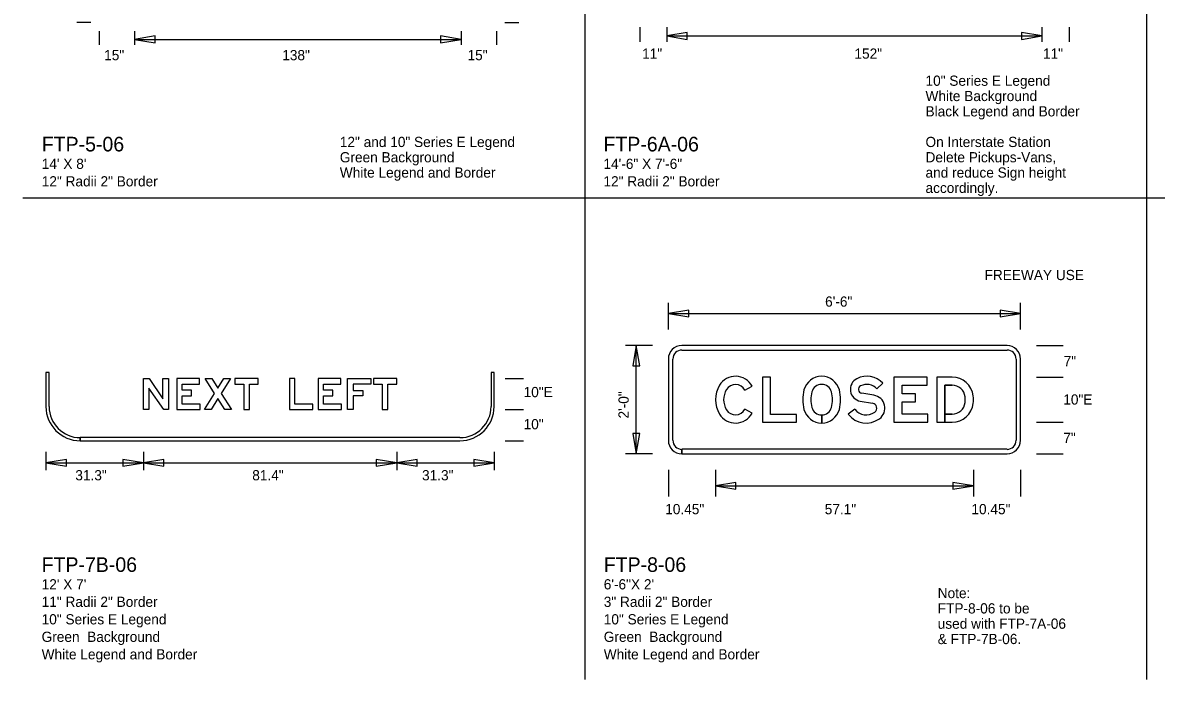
# Model space of a CAD drawing. Extents: x 0 to 770, y 0 to 495.
# Drawn here: x 0 to 388.5, y 0 to 225.2 of the extents above; entities that cross this region are included whole.
import ezdxf

# ---------------------------------------------------------------- set-up
doc = ezdxf.new("R2010")
doc.units = 0
for name, color, linetype in [('Dimension', 7, 'Continuous'), ('GSBWFill', 7, 'Continuous'), ('GSColorFill', 7, 'Continuous'), ('GSDims', 7, 'Continuous'), ('GSOutline', 7, 'Continuous'), ('SheetLines_dp', 7, 'Continuous'), ('TextStructures', 7, 'Continuous')]:
    doc.layers.add(name, color=color, linetype=linetype)

msp = doc.modelspace()

# ---------------------------------------------------------------- linework, layer by layer
at = {"layer": 'Dimension'}
for points in [[(220.78, 220.64), (227.79, 219.46), (227.79, 221.83)], [(349.34, 220.64), (342.33, 221.83), (342.33, 219.46)], [(38.38, 219.43), (45.4, 218.25), (45.4, 220.62)], [(150.27, 219.43), (143.25, 220.62), (143.25, 218.25)], [(221.28, 125.44), (228.3, 124.25), (228.3, 126.63)], [(342, 125.44), (334.99, 126.63), (334.99, 124.25)], [(210.31, 114.47), (209.12, 107.46), (211.5, 107.46)], [(210.31, 77.33), (211.5, 84.34), (209.12, 84.34)], [(7.98, 74.26), (14.99, 73.07), (14.99, 75.44)], [(41.37, 74.26), (34.35, 75.44), (34.35, 73.07)], [(41.37, 74.26), (48.39, 73.07), (48.39, 75.44)], [(128.21, 74.26), (121.19, 75.44), (121.19, 73.07)], [(128.21, 74.26), (135.22, 73.07), (135.22, 75.44)], [(161.6, 74.26), (154.58, 75.44), (154.58, 73.07)], [(237.45, 66.36), (244.47, 65.17), (244.47, 67.55)], [(325.83, 66.36), (318.81, 67.55), (318.81, 65.17)]]:
    msp.add_lwpolyline(points, close=True, dxfattribs=at)
at = {"layer": 'GSBWFill'}
for p, q in [((337.36, 114.47), (225.92, 114.47)), ((337.36, 114.47), (225.92, 114.47)), ((225.92, 112.93), (337.36, 112.93)), ((221.28, 109.83), (221.28, 81.97)), ((221.28, 109.83), (221.28, 81.97)), ((222.83, 81.97), (222.83, 109.83)), ((340.46, 109.83), (340.46, 81.97)), ((342, 81.97), (342, 109.83)), ((342, 81.97), (342, 109.83)), ((7.98, 105.19), (7.98, 93.55)), ((7.98, 105.19), (7.98, 93.55)), ((9.04, 93.55), (9.04, 105.19)), ((160.53, 105.19), (160.53, 93.55)), ((161.6, 93.55), (161.6, 105.19)), ((161.6, 93.55), (161.6, 105.19)), ((292.76, 99.62), (294.8, 101.51)), ((247.53, 99.2), (249.99, 100.51)), ((291.75, 97.43), (287.54, 98.14)), ((287.07, 95.4), (291.29, 94.68)), ((249.99, 91.3), (247.53, 92.61)), ((247.53, 92.61), (247.53, 92.61)), ((273.83, 87.89), (273.83, 90.68)), ((273.83, 90.68), (273.83, 87.89)), ((285.17, 92.61), (282.96, 90.91)), ((316.08, 88.16), (318.53, 88.16)), ((19.71, 81.82), (19.71, 82.88)), ((19.71, 81.82), (149.86, 81.82)), ((149.86, 82.88), (19.72, 82.88)), ((19.72, 82.88), (19.72, 81.82)), ((19.72, 81.82), (149.86, 81.82)), ((225.92, 77.33), (225.92, 78.88)), ((337.36, 78.88), (225.94, 78.88)), ((225.94, 78.88), (225.94, 77.33)), ((225.92, 77.33), (337.36, 77.33)), ((225.94, 77.33), (337.36, 77.33))]:
    msp.add_line(p, q, dxfattribs=at)
for points in [[(9.04, 105.19), (7.98, 105.19)], [(161.6, 105.19), (160.53, 105.19)], [(318.53, 103.64), (313.29, 103.64), (313.29, 88.16), (316.08, 88.16), (316.08, 100.85), (318.53, 100.85)], [(318.53, 90.95), (316.08, 90.95), (316.08, 88.16)]]:
    msp.add_lwpolyline(points, dxfattribs=at)
for points in [[(50.01, 103.15), (50.01, 92.48), (48.36, 92.48), (43.29, 99.79), (43.29, 92.48), (41.37, 92.48), (41.37, 103.15), (43.3, 103.15), (48.09, 96.24), (48.09, 103.15)], [(60.78, 94.41), (54.7, 94.41), (54.7, 97.27), (57.85, 97.27), (57.85, 99.19), (54.7, 99.19), (54.7, 101.23), (60.62, 101.23), (60.62, 103.15), (52.78, 103.15), (52.78, 92.48), (60.78, 92.48)], [(69.29, 92.48), (66.92, 96.27), (64.55, 92.48), (62.28, 92.48), (65.79, 98.07), (62.6, 103.15), (64.87, 103.15), (66.92, 99.88), (68.97, 103.15), (71.24, 103.15), (68.05, 98.07), (71.56, 92.48)], [(72.73, 101.23), (75.77, 101.23), (75.77, 92.48), (77.69, 92.48), (77.69, 101.23), (80.73, 101.23), (80.73, 103.15), (72.73, 103.15)], [(99.4, 92.48), (99.4, 94.35), (93.32, 94.35), (93.32, 103.15), (91.4, 103.15), (91.4, 92.48)], [(109.22, 94.41), (103.14, 94.41), (103.14, 97.27), (106.28, 97.27), (106.28, 99.19), (103.14, 99.19), (103.14, 101.23), (109.06, 101.23), (109.06, 103.15), (101.22, 103.15), (101.22, 92.48), (109.22, 92.48)], [(113.27, 97.18), (113.27, 92.48), (111.35, 92.48), (111.35, 103.15), (119.35, 103.15), (119.35, 101.23), (113.27, 101.23), (113.27, 99.1), (116.63, 99.1), (116.63, 97.18)], [(120.21, 101.23), (123.25, 101.23), (123.25, 92.48), (125.17, 92.48), (125.17, 101.23), (128.21, 101.23), (128.21, 103.15), (120.21, 103.15)], [(265.16, 88.16), (265.16, 90.87), (256.34, 90.87), (256.34, 103.64), (253.55, 103.64), (253.55, 88.16)], [(310.2, 90.95), (301.38, 90.95), (301.38, 95.11), (305.94, 95.11), (305.94, 97.9), (301.38, 97.9), (301.38, 100.85), (309.97, 100.85), (309.97, 103.64), (298.59, 103.64), (298.59, 88.16), (310.2, 88.16)]]:
    msp.add_lwpolyline(points, close=True, dxfattribs=at)
for centre, radius, start, end in [((225.92, 109.83), 4.64, 90, 180), ((225.92, 109.83), 4.64, 90, 180), ((225.92, 109.83), 3.1, 90, 180), ((337.36, 109.83), 4.64, 0, 90), ((337.36, 109.83), 4.64, 0, 90), ((337.36, 109.83), 3.1, 0, 90), ((244.32, 97.49), 6.42, 28.0265, 148.7499), ((244.32, 97.49), 3.64, 28.0265, 148.7499), ((273.83, 97.64), 6.27, 14.9618, 165.0382), ((273.83, 97.64), 3.49, 14.9618, 165.0382), ((287.76, 99.44), 4.1, 116.9123, 260.4087), ((289.3, 96.4), 7.51, 42.8759, 116.9123), ((289.3, 96.4), 4.72, 42.8759, 116.9123), ((318.53, 96.36), 7.27, 6.5003, 90), ((246.94, 95.9), 9.48, 148.7499, 211.2501), ((246.94, 95.9), 6.7, 148.7499, 211.2501), ((280.33, 95.9), 13, 165.0382, 194.9618), ((280.33, 95.9), 10.22, 165.0382, 194.9618), ((267.33, 95.9), 10.22, 345.0382, 14.9618), ((267.33, 95.9), 13, 345.0382, 14.9618), ((287.76, 99.44), 1.32, 116.9123, 260.4087), ((291.01, 93), 4.49, 306.123, 80.4087), ((318.53, 96.36), 4.49, 6.5002, 90), ((314.45, 95.9), 11.38, 353.4998, 6.5002), ((19.71, 93.55), 11.73, 180, 270), ((19.71, 93.55), 11.73, 180, 270), ((19.71, 93.55), 10.67, 180, 270), ((149.86, 93.55), 10.67, 270, 0), ((149.86, 93.55), 11.73, 270, 0), ((149.86, 93.55), 11.73, 270, 0), ((273.83, 94.16), 3.49, 194.9618, 270), ((273.83, 94.16), 3.49, 270.0127, 345.0382), ((291.01, 93), 1.7, 306.123, 80.4087), ((318.53, 95.44), 4.49, 270, 353.4998), ((318.53, 95.44), 7.27, 270, 353.4998), ((314.45, 95.9), 8.59, 353.4998, 6.5003), ((244.32, 94.31), 6.42, 211.2501, 331.9735), ((244.32, 94.31), 3.64, 211.2501, 331.9735), ((273.83, 94.16), 6.27, 194.9618, 270), ((273.83, 94.16), 6.27, 270.0071, 345.0382), ((289.09, 95.63), 7.74, 217.5895, 306.123), ((289.09, 95.63), 4.95, 217.5895, 306.123), ((225.92, 81.97), 4.64, 180, 270), ((225.92, 81.97), 4.64, 180, 270), ((225.92, 81.97), 3.1, 180, 270), ((337.36, 81.97), 4.64, 270, 0), ((337.36, 81.97), 3.1, 270, 0), ((337.36, 81.97), 4.64, 270, 0)]:
    msp.add_arc(centre, radius, start, end, dxfattribs=at)
at = {"layer": 'GSColorFill'}
for p, q in [((292.76, 99.62), (294.8, 101.51)), ((247.53, 99.2), (249.99, 100.51)), ((291.75, 97.43), (287.54, 98.14)), ((287.07, 95.4), (291.29, 94.68)), ((249.99, 91.3), (247.53, 92.61)), ((247.53, 92.61), (247.53, 92.61)), ((273.83, 87.89), (273.83, 90.68)), ((273.83, 90.68), (273.83, 87.89)), ((285.17, 92.61), (282.96, 90.91)), ((316.08, 88.16), (318.53, 88.16))]:
    msp.add_line(p, q, dxfattribs=at)
for points in [[(50.01, 103.15), (50.01, 92.48), (48.36, 92.48), (43.29, 99.79), (43.29, 92.48), (41.37, 92.48), (41.37, 103.15), (43.3, 103.15), (48.09, 96.24), (48.09, 103.15)], [(60.78, 94.41), (54.7, 94.41), (54.7, 97.27), (57.85, 97.27), (57.85, 99.19), (54.7, 99.19), (54.7, 101.23), (60.62, 101.23), (60.62, 103.15), (52.78, 103.15), (52.78, 92.48), (60.78, 92.48)], [(69.29, 92.48), (66.92, 96.27), (64.55, 92.48), (62.28, 92.48), (65.79, 98.07), (62.6, 103.15), (64.87, 103.15), (66.92, 99.88), (68.97, 103.15), (71.24, 103.15), (68.05, 98.07), (71.56, 92.48)], [(72.73, 101.23), (75.77, 101.23), (75.77, 92.48), (77.69, 92.48), (77.69, 101.23), (80.73, 101.23), (80.73, 103.15), (72.73, 103.15)], [(99.4, 92.48), (99.4, 94.35), (93.32, 94.35), (93.32, 103.15), (91.4, 103.15), (91.4, 92.48)], [(109.22, 94.41), (103.14, 94.41), (103.14, 97.27), (106.28, 97.27), (106.28, 99.19), (103.14, 99.19), (103.14, 101.23), (109.06, 101.23), (109.06, 103.15), (101.22, 103.15), (101.22, 92.48), (109.22, 92.48)], [(113.27, 97.18), (113.27, 92.48), (111.35, 92.48), (111.35, 103.15), (119.35, 103.15), (119.35, 101.23), (113.27, 101.23), (113.27, 99.1), (116.63, 99.1), (116.63, 97.18)], [(120.21, 101.23), (123.25, 101.23), (123.25, 92.48), (125.17, 92.48), (125.17, 101.23), (128.21, 101.23), (128.21, 103.15), (120.21, 103.15)], [(265.16, 88.16), (265.16, 90.87), (256.34, 90.87), (256.34, 103.64), (253.55, 103.64), (253.55, 88.16)], [(310.2, 90.95), (301.38, 90.95), (301.38, 95.11), (305.94, 95.11), (305.94, 97.9), (301.38, 97.9), (301.38, 100.85), (309.97, 100.85), (309.97, 103.64), (298.59, 103.64), (298.59, 88.16), (310.2, 88.16)]]:
    msp.add_lwpolyline(points, close=True, dxfattribs=at)
for points in [[(318.53, 103.64), (313.29, 103.64), (313.29, 88.16), (316.08, 88.16), (316.08, 100.85), (318.53, 100.85)], [(318.53, 90.95), (316.08, 90.95), (316.08, 88.16)]]:
    msp.add_lwpolyline(points, dxfattribs=at)
for centre, radius, start, end in [((244.32, 97.49), 6.42, 28.0265, 148.7499), ((244.32, 97.49), 3.64, 28.0265, 148.7499), ((273.83, 97.64), 6.27, 14.9618, 165.0382), ((273.83, 97.64), 3.49, 14.9618, 165.0382), ((287.76, 99.44), 4.1, 116.9123, 260.4087), ((289.3, 96.4), 7.51, 42.8759, 116.9123), ((289.3, 96.4), 4.72, 42.8759, 116.9123), ((318.53, 96.36), 7.27, 6.5003, 90), ((246.94, 95.9), 9.48, 148.7499, 211.2501), ((246.94, 95.9), 6.7, 148.7499, 211.2501), ((280.33, 95.9), 13, 165.0382, 194.9618), ((280.33, 95.9), 10.22, 165.0382, 194.9618), ((267.33, 95.9), 10.22, 345.0382, 14.9618), ((267.33, 95.9), 13, 345.0382, 14.9618), ((287.76, 99.44), 1.32, 116.9123, 260.4087), ((291.01, 93), 4.49, 306.123, 80.4087), ((318.53, 96.36), 4.49, 6.5002, 90), ((314.45, 95.9), 11.38, 353.4998, 6.5002), ((273.83, 94.16), 3.49, 194.9618, 270), ((273.83, 94.16), 3.49, 270.0127, 345.0382), ((291.01, 93), 1.7, 306.123, 80.4087), ((318.53, 95.44), 4.49, 270, 353.4998), ((318.53, 95.44), 7.27, 270, 353.4998), ((314.45, 95.9), 8.59, 353.4998, 6.5003), ((244.32, 94.31), 6.42, 211.2501, 331.9735), ((244.32, 94.31), 3.64, 211.2501, 331.9735), ((273.83, 94.16), 6.27, 194.9618, 270), ((273.83, 94.16), 6.27, 270.0071, 345.0382), ((289.09, 95.63), 7.74, 217.5895, 306.123), ((289.09, 95.63), 4.95, 217.5895, 306.123)]:
    msp.add_arc(centre, radius, start, end, dxfattribs=at)
at = {"layer": 'GSDims'}
for p, q in [((23.35, 225.18), (18.56, 225.18)), ((26.22, 222.31), (26.22, 217.52)), ((38.38, 222.31), (38.38, 217.52)), ((38.38, 222.31), (38.38, 217.52)), ((150.27, 222.31), (150.27, 217.52)), ((150.27, 222.31), (150.27, 217.52)), ((162.43, 222.31), (162.43, 217.52)), ((165.3, 225.18), (170.09, 225.18)), ((211.47, 223.64), (211.47, 218.65)), ((220.78, 223.64), (220.78, 218.65)), ((220.78, 223.64), (220.78, 218.65)), ((349.34, 223.64), (349.34, 218.65)), ((349.34, 223.64), (349.34, 218.65)), ((358.65, 223.64), (358.65, 218.65)), ((38.38, 219.43), (150.27, 219.43)), ((220.78, 220.64), (349.34, 220.64)), ((221.28, 119.96), (221.28, 129.1)), ((342, 119.96), (342, 129.1)), ((221.28, 125.44), (342, 125.44)), ((215.8, 114.47), (206.65, 114.47)), ((210.31, 77.33), (210.31, 114.47)), ((347.49, 114.47), (356.63, 114.47)), ((165.38, 103.15), (171.68, 103.15)), ((165.38, 103.15), (171.68, 103.15)), ((347.49, 103.64), (356.63, 103.64)), ((347.49, 103.64), (356.63, 103.64)), ((165.38, 92.48), (171.68, 92.48)), ((165.38, 92.48), (171.68, 92.48)), ((347.49, 88.16), (356.63, 88.16)), ((347.49, 88.16), (356.63, 88.16)), ((165.38, 81.82), (171.68, 81.82)), ((7.98, 78.04), (7.98, 71.74)), ((41.37, 78.04), (41.37, 71.74)), ((41.37, 78.04), (41.37, 71.74)), ((128.21, 78.04), (128.21, 71.74)), ((128.21, 78.04), (128.21, 71.74)), ((161.6, 78.04), (161.6, 71.74)), ((7.98, 74.26), (41.37, 74.26)), ((41.37, 74.26), (128.21, 74.26)), ((128.21, 74.26), (161.6, 74.26)), ((215.8, 77.33), (206.65, 77.33)), ((347.49, 77.33), (356.63, 77.33)), ((221.28, 71.84), (221.28, 62.7)), ((237.45, 71.84), (237.45, 62.7)), ((237.45, 71.84), (237.45, 62.7)), ((325.83, 71.84), (325.83, 62.7)), ((325.83, 71.84), (325.83, 62.7)), ((342, 71.84), (342, 62.7)), ((237.45, 66.36), (325.83, 66.36))]:
    msp.add_line(p, q, dxfattribs=at)
at = {"layer": 'GSOutline'}
for p, q in [((292.76, 99.62), (294.8, 101.51)), ((247.53, 99.2), (249.99, 100.51)), ((291.75, 97.43), (287.54, 98.14)), ((287.07, 95.4), (291.29, 94.68)), ((249.99, 91.3), (247.53, 92.61)), ((247.53, 92.61), (247.53, 92.61)), ((285.17, 92.61), (282.96, 90.91)), ((316.08, 90.95), (318.53, 90.95))]:
    msp.add_line(p, q, dxfattribs=at)
for points in [[(50.01, 103.15), (50.01, 92.48), (48.36, 92.48), (43.29, 99.79), (43.29, 92.48), (41.37, 92.48), (41.37, 103.15), (43.3, 103.15), (48.09, 96.24), (48.09, 103.15)], [(60.78, 94.41), (54.7, 94.41), (54.7, 97.27), (57.85, 97.27), (57.85, 99.19), (54.7, 99.19), (54.7, 101.23), (60.62, 101.23), (60.62, 103.15), (52.78, 103.15), (52.78, 92.48), (60.78, 92.48)], [(69.29, 92.48), (66.92, 96.27), (64.55, 92.48), (62.28, 92.48), (65.79, 98.07), (62.6, 103.15), (64.87, 103.15), (66.92, 99.88), (68.97, 103.15), (71.24, 103.15), (68.05, 98.07), (71.56, 92.48)], [(72.73, 101.23), (75.77, 101.23), (75.77, 92.48), (77.69, 92.48), (77.69, 101.23), (80.73, 101.23), (80.73, 103.15), (72.73, 103.15)], [(99.4, 92.48), (99.4, 94.35), (93.32, 94.35), (93.32, 103.15), (91.4, 103.15), (91.4, 92.48)], [(109.22, 94.41), (103.14, 94.41), (103.14, 97.27), (106.28, 97.27), (106.28, 99.19), (103.14, 99.19), (103.14, 101.23), (109.06, 101.23), (109.06, 103.15), (101.22, 103.15), (101.22, 92.48), (109.22, 92.48)], [(113.27, 97.18), (113.27, 92.48), (111.35, 92.48), (111.35, 103.15), (119.35, 103.15), (119.35, 101.23), (113.27, 101.23), (113.27, 99.1), (116.63, 99.1), (116.63, 97.18)], [(120.21, 101.23), (123.25, 101.23), (123.25, 92.48), (125.17, 92.48), (125.17, 101.23), (128.21, 101.23), (128.21, 103.15), (120.21, 103.15)], [(265.16, 88.16), (265.16, 90.87), (256.34, 90.87), (256.34, 103.64), (253.55, 103.64), (253.55, 88.16)], [(310.2, 90.95), (301.38, 90.95), (301.38, 95.11), (305.94, 95.11), (305.94, 97.9), (301.38, 97.9), (301.38, 100.85), (309.97, 100.85), (309.97, 103.64), (298.59, 103.64), (298.59, 88.16), (310.2, 88.16)]]:
    msp.add_lwpolyline(points, close=True, dxfattribs=at)
for points in [[(318.53, 103.64), (313.29, 103.64), (313.29, 88.16), (318.53, 88.16)], [(318.53, 100.85), (316.08, 100.85), (316.08, 90.95)]]:
    msp.add_lwpolyline(points, dxfattribs=at)
for centre, radius, start, end in [((244.32, 97.49), 6.42, 28.0265, 148.7499), ((244.32, 97.49), 3.64, 28.0265, 148.7499), ((273.83, 97.64), 6.27, 14.9618, 165.0382), ((273.83, 97.64), 3.49, 14.9618, 165.0382), ((287.76, 99.44), 4.1, 116.9123, 260.4087), ((289.3, 96.4), 7.51, 42.8759, 116.9123), ((289.3, 96.4), 4.72, 42.8759, 116.9123), ((318.53, 96.36), 7.27, 6.5003, 90), ((246.94, 95.9), 9.48, 148.7499, 211.2501), ((246.94, 95.9), 6.7, 148.7499, 211.2501), ((280.33, 95.9), 13, 165.0382, 194.9618), ((280.33, 95.9), 10.22, 165.0382, 194.9618), ((267.33, 95.9), 10.22, 345.0382, 14.9618), ((267.33, 95.9), 13, 345.0382, 14.9618), ((287.76, 99.44), 1.32, 116.9123, 260.4087), ((291.01, 93), 4.49, 306.123, 80.4087), ((318.53, 96.36), 4.49, 6.5003, 90), ((314.45, 95.9), 11.38, 353.4998, 6.5002), ((273.83, 94.16), 3.49, 194.9618, 345.0382), ((291.01, 93), 1.7, 306.123, 80.4087), ((318.53, 95.44), 4.49, 270, 353.4998), ((318.53, 95.44), 7.27, 270, 353.4998), ((314.45, 95.9), 8.59, 353.4998, 6.5002), ((244.32, 94.31), 6.42, 211.2501, 331.9735), ((244.32, 94.31), 3.64, 211.2501, 331.9735), ((273.83, 94.16), 6.27, 194.9618, 345.0382), ((289.09, 95.63), 7.74, 217.5895, 306.123), ((289.09, 95.63), 4.95, 217.5895, 306.123)]:
    msp.add_arc(centre, radius, start, end, dxfattribs=at)
at = {"layer": 'SheetLines_dp'}
for p, q in [((192.8, 0), (192.8, 495)), ((385.3, 0), (385.3, 495)), ((770, 165), (0, 165))]:
    msp.add_line(p, q, dxfattribs=at)

# ---------------------------------------------------------------- texts
at = {"layer": 'TextStructures'}
for s, height, p in [('15"', 3.5, (27.93, 212.3)), ('138"', 3.5, (88.96, 212.3)), ('15"', 3.5, (152.46, 212.3)), ('11"', 3.5, (212.3, 212.82)), ('152"', 3.5, (285.06, 212.82)), ('11"', 3.5, (349.67, 212.82)), ('10" Series E Legend', 3.5, (309.42, 203.53)), ('White Background', 3.5, (309.42, 198.28)), ('Black Legend and Border', 3.5, (309.42, 193.03)), ('FTP-5-06', 5, (6.54, 181.03)), ('12" and 10" Series E Legend', 3.5, (108.69, 182.53)), ('FTP-6A-06', 5, (199.05, 181.03)), ('On Interstate Station', 3.5, (309.42, 182.53)), ('Green Background', 3.5, (108.69, 177.28)), ('Delete Pickups-Vans,', 3.5, (309.42, 177.28)), ("14' X 8'", 3.5, (6.54, 175.03)), ('White Legend and Border', 3.5, (108.69, 172.03)), ('14\'-6" X 7\'-6"', 3.5, (199.05, 175.03)), ('and reduce Sign height', 3.5, (309.42, 172.03)), ('12" Radii 2" Border', 3.5, (6.54, 169.03)), ('12" Radii 2" Border', 3.5, (199.05, 169.03)), ('accordingly.', 3.5, (309.42, 166.78)), ('FREEWAY USE', 3.5, (329.65, 136.9)), ('6\'-6"', 3.5, (275.01, 127.79)), ('7"', 3.5, (356.76, 107.36)), ('10"E', 3.5, (171.68, 96.76)), ('10"E', 3.5, (356.63, 94.21)), ('10"', 3.5, (171.68, 85.75)), ('7"', 3.5, (356.63, 81.05)), ('31.3"', 3.5, (18.04, 68.24)), ('81.4"', 3.5, (78.68, 68.24)), ('31.3"', 3.5, (136.87, 68.24)), ('10.45"', 3.5, (220.21, 56.62)), ('57.1"', 3.5, (274.88, 56.62)), ('10.45"', 3.5, (325.15, 56.62)), ('FTP-7B-06', 5, (6.5, 36.84)), ('FTP-8-06', 5, (199.15, 36.84)), ("12' X 7'", 3.5, (6.5, 30.84)), ('6\'-6"X 2\'', 3.5, (199.15, 30.84)), ('Note:', 3.5, (313.6, 27.84)), ('11" Radii 2" Border', 3.5, (6.5, 24.84)), ('3" Radii 2" Border', 3.5, (199.15, 24.84)), ('FTP-8-06 to be', 3.5, (313.6, 22.59)), ('10" Series E Legend', 3.5, (6.5, 18.84)), ('10" Series E Legend', 3.5, (199.15, 18.84)), ('used with FTP-7A-06', 3.5, (313.6, 17.34)), ('Green  Background', 3.5, (6.5, 12.84)), ('Green  Background', 3.5, (199.15, 12.84)), ('& FTP-7B-06.', 3.5, (313.6, 12.09)), ('White Legend and Border', 3.5, (6.5, 6.84)), ('White Legend and Border', 3.5, (199.15, 6.84))]:
    msp.add_text(s, height=height, dxfattribs=at).set_placement(p)
msp.add_text('2\'-0"', height=3.5, rotation=90, dxfattribs=at).set_placement((207.69, 89.44))

doc.saveas('drawing.dxf')
